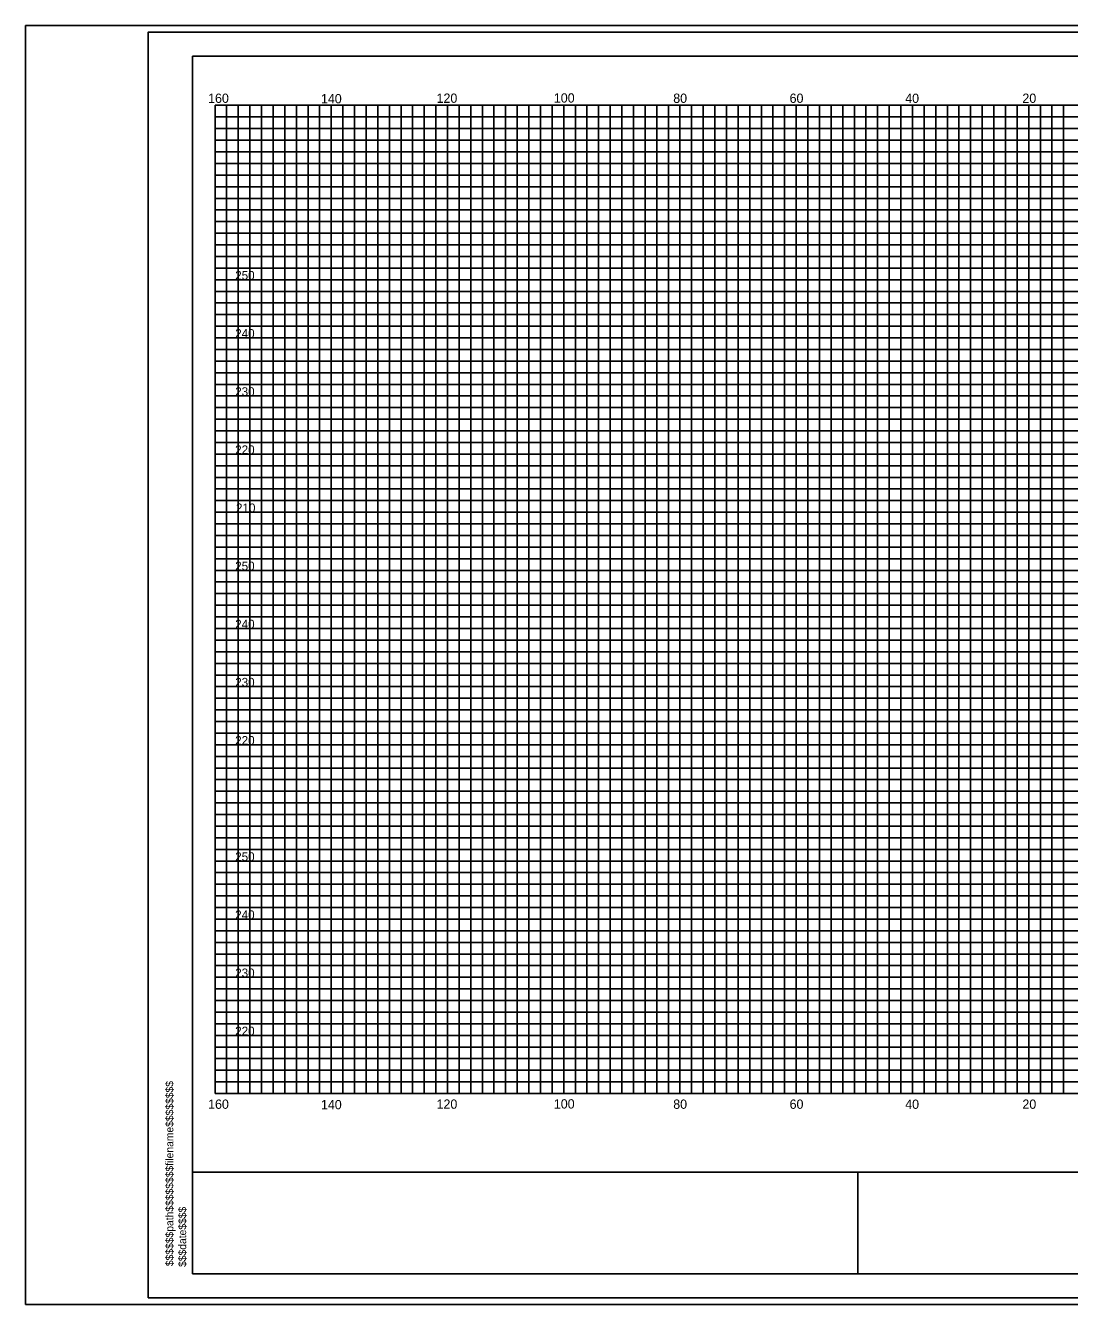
# Model space of a CAD drawing. Extents: x 967 to 1326, y 964 to 1744.
# Drawn here: x 967.4 to 1147, y 1243.7 to 1463.7 of the extents above; entities that cross this region are included whole.
import ezdxf

# ---------------------------------------------------------------- set-up
doc = ezdxf.new("R2010")
doc.units = 0
for name, color, linetype in [('Default', 7, 'Continuous'), ('RD_PD_PaveShd', 7, 'Continuous'), ('RD_XS_CurbBase', 7, 'Continuous'), ('RD_XS_TX_Elev_PR', 7, 'Continuous'), ('RD_XS_TX_MkPT', 7, 'Continuous'), ('RD_XS_TX_Slope', 7, 'Continuous'), ('RD_XS_TX_TOC', 7, 'Continuous')]:
    doc.layers.add(name, color=color, linetype=linetype)

msp = doc.modelspace()

# ---------------------------------------------------------------- linework, layer by layer
at = {"layer": 'RD_PD_PaveShd'}
for p, q in [((996.11, 1248.98), (996.11, 1458.46)), ((996.11, 1458.46), (1323.89, 1458.46)), ((996.11, 1266.49), (1323.89, 1266.49)), ((1110.59, 1248.98), (1110.59, 1266.56)), ((1323.89, 1248.98), (996.11, 1248.98))]:
    msp.add_line(p, q, dxfattribs=at)
at = {"layer": 'RD_XS_CurbBase'}
msp.add_lwpolyline([(967.41, 1243.72), (1326.28, 1243.72), (1326.28, 1463.72), (967.41, 1463.72)], close=True, dxfattribs=at)
at = {"layer": 'RD_XS_TX_Elev_PR'}
for p, q in [((1000, 1450), (1320, 1450)), ((1000, 1280), (1000, 1450)), ((1010, 1280), (1010, 1450)), ((1020, 1280), (1020, 1450)), ((1030, 1280), (1030, 1450)), ((1040, 1280), (1040, 1450)), ((1050, 1280), (1050, 1450)), ((1060, 1280), (1060, 1450)), ((1070, 1280), (1070, 1450)), ((1080, 1280), (1080, 1450)), ((1090, 1280), (1090, 1450)), ((1100, 1280), (1100, 1450)), ((1110, 1280), (1110, 1450)), ((1120, 1280), (1120, 1450)), ((1130, 1280), (1130, 1450)), ((1140, 1280), (1140, 1450)), ((1000, 1440), (1320, 1440)), ((1000, 1430), (1320, 1430)), ((1000, 1420), (1320, 1420)), ((1000, 1410), (1320, 1410)), ((1000, 1400), (1320, 1400)), ((1000, 1390), (1320, 1390)), ((1000, 1380), (1320, 1380)), ((1000, 1370), (1320, 1370)), ((1000, 1360), (1320, 1360)), ((1000, 1350), (1320, 1350)), ((1000, 1340), (1320, 1340)), ((1000, 1330), (1320, 1330)), ((1000, 1320), (1320, 1320)), ((1000, 1310), (1320, 1310)), ((1000, 1300), (1320, 1300)), ((1000, 1290), (1320, 1290)), ((1000, 1280), (1320, 1280))]:
    msp.add_line(p, q, dxfattribs=at)
at = {"layer": 'RD_XS_TX_Slope'}
for p, q in [((1002, 1280), (1002, 1450)), ((1004, 1280), (1004, 1450)), ((1006, 1280), (1006, 1450)), ((1008, 1280), (1008, 1450)), ((1012, 1280), (1012, 1450)), ((1014, 1280), (1014, 1450)), ((1016, 1280), (1016, 1450)), ((1018, 1280), (1018, 1450)), ((1022, 1280), (1022, 1450)), ((1024, 1280), (1024, 1450)), ((1026, 1280), (1026, 1450)), ((1028, 1280), (1028, 1450)), ((1032, 1280), (1032, 1450)), ((1034, 1280), (1034, 1450)), ((1036, 1280), (1036, 1450)), ((1038, 1280), (1038, 1450)), ((1042, 1280), (1042, 1450)), ((1044, 1280), (1044, 1450)), ((1046, 1280), (1046, 1450)), ((1048, 1280), (1048, 1450)), ((1052, 1280), (1052, 1450)), ((1054, 1280), (1054, 1450)), ((1056, 1280), (1056, 1450)), ((1058, 1280), (1058, 1450)), ((1062, 1280), (1062, 1450)), ((1064, 1280), (1064, 1450)), ((1066, 1280), (1066, 1450)), ((1068, 1280), (1068, 1450)), ((1072, 1280), (1072, 1450)), ((1074, 1280), (1074, 1450)), ((1076, 1280), (1076, 1450)), ((1078, 1280), (1078, 1450)), ((1082, 1280), (1082, 1450)), ((1084, 1280), (1084, 1450)), ((1086, 1280), (1086, 1450)), ((1088, 1280), (1088, 1450)), ((1092, 1280), (1092, 1450)), ((1094, 1280), (1094, 1450)), ((1096, 1280), (1096, 1450)), ((1098, 1280), (1098, 1450)), ((1102, 1280), (1102, 1450)), ((1104, 1280), (1104, 1450)), ((1106, 1280), (1106, 1450)), ((1108, 1280), (1108, 1450)), ((1112, 1280), (1112, 1450)), ((1114, 1280), (1114, 1450)), ((1116, 1280), (1116, 1450)), ((1118, 1280), (1118, 1450)), ((1122, 1280), (1122, 1450)), ((1124, 1280), (1124, 1450)), ((1126, 1280), (1126, 1450)), ((1128, 1280), (1128, 1450)), ((1132, 1280), (1132, 1450)), ((1134, 1280), (1134, 1450)), ((1136, 1280), (1136, 1450)), ((1138, 1280), (1138, 1450)), ((1142, 1280), (1142, 1450)), ((1144, 1280), (1144, 1450)), ((1146, 1280), (1146, 1450)), ((1000, 1448), (1320, 1448)), ((1000, 1446), (1320, 1446)), ((1000, 1444), (1320, 1444)), ((1000, 1442), (1320, 1442)), ((1000, 1438), (1320, 1438)), ((1000, 1436), (1320, 1436)), ((1000, 1434), (1320, 1434)), ((1000, 1432), (1320, 1432)), ((1000, 1428), (1320, 1428)), ((1000, 1426), (1320, 1426)), ((1000, 1424), (1320, 1424)), ((1000, 1422), (1320, 1422)), ((1000, 1418), (1320, 1418)), ((1000, 1416), (1320, 1416)), ((1000, 1414), (1320, 1414)), ((1000, 1412), (1320, 1412)), ((1000, 1408), (1320, 1408)), ((1000, 1406), (1320, 1406)), ((1000, 1404), (1320, 1404)), ((1000, 1402), (1320, 1402)), ((1000, 1398), (1320, 1398)), ((1000, 1396), (1320, 1396)), ((1000, 1394), (1320, 1394)), ((1000, 1392), (1320, 1392)), ((1000, 1388), (1320, 1388)), ((1000, 1386), (1320, 1386)), ((1000, 1384), (1320, 1384)), ((1000, 1382), (1320, 1382)), ((1000, 1378), (1320, 1378)), ((1000, 1376), (1320, 1376)), ((1000, 1374), (1320, 1374)), ((1000, 1372), (1320, 1372)), ((1000, 1368), (1320, 1368)), ((1000, 1366), (1320, 1366)), ((1000, 1364), (1320, 1364)), ((1000, 1362), (1320, 1362)), ((1000, 1358), (1320, 1358)), ((1000, 1356), (1320, 1356)), ((1000, 1354), (1320, 1354)), ((1000, 1352), (1320, 1352)), ((1000, 1348), (1320, 1348)), ((1000, 1346), (1320, 1346)), ((1000, 1344), (1320, 1344)), ((1000, 1342), (1320, 1342)), ((1000, 1338), (1320, 1338)), ((1000, 1336), (1320, 1336)), ((1000, 1334), (1320, 1334)), ((1000, 1332), (1320, 1332)), ((1000, 1328), (1320, 1328)), ((1000, 1326), (1320, 1326)), ((1000, 1324), (1320, 1324)), ((1000, 1322), (1320, 1322)), ((1000, 1318), (1320, 1318)), ((1000, 1316), (1320, 1316)), ((1000, 1314), (1320, 1314)), ((1000, 1312), (1320, 1312)), ((1000, 1308), (1320, 1308)), ((1000, 1306), (1320, 1306)), ((1000, 1304), (1320, 1304)), ((1000, 1302), (1320, 1302)), ((1000, 1298), (1320, 1298)), ((1000, 1296), (1320, 1296)), ((1000, 1294), (1320, 1294)), ((1000, 1292), (1320, 1292)), ((1000, 1288), (1320, 1288)), ((1000, 1286), (1320, 1286)), ((1000, 1284), (1320, 1284)), ((1000, 1282), (1320, 1282))]:
    msp.add_line(p, q, dxfattribs=at)
at = {"layer": 'RD_XS_TX_TOC'}
for points in [[(967.41, 1243.72), (1326.28, 1243.72), (1326.28, 1463.72), (967.41, 1463.72)], [(988.52, 1244.84), (1326.28, 1244.84), (1326.28, 1462.6), (988.52, 1462.6)]]:
    msp.add_lwpolyline(points, close=True, dxfattribs=at)

# ---------------------------------------------------------------- texts
at = {"layer": 'Default'}
for s, p in [('250', (1003.47, 1420)), ('240', (1003.47, 1410)), ('230', (1003.47, 1400)), ('220', (1003.47, 1390)), ('210', (1003.61, 1380)), ('250', (1003.47, 1370)), ('240', (1003.47, 1360)), ('230', (1003.47, 1350)), ('220', (1003.47, 1340)), ('250', (1003.47, 1320)), ('240', (1003.47, 1310)), ('230', (1003.47, 1300)), ('220', (1003.47, 1290))]:
    msp.add_text(s, height=1.5, dxfattribs=at).set_placement(p)
for s, p in [('$$$$$$path$$$$$$$$filename$$$$$$$$', (992.83, 1250.31)), ('$$$date$$$$', (995.04, 1250.17))]:
    msp.add_text(s, height=1.3258, rotation=90, dxfattribs=at).set_placement(p)
at = {"layer": 'RD_XS_TX_MkPT'}
for s, p in [('160', (998.81, 1450.42)), ('120', (1038.12, 1450.43)), ('100', (1058.3, 1450.47)), ('80', (1078.84, 1450.42)), ('60', (1098.86, 1450.42)), ('40', (1118.75, 1450.41)), ('20', (1138.91, 1450.42)), ('140', (1018.23, 1450.34)), ('160', (998.81, 1277.37)), ('140', (1018.23, 1277.29)), ('120', (1038.12, 1277.38)), ('100', (1058.3, 1277.42)), ('80', (1078.84, 1277.37)), ('60', (1098.86, 1277.37)), ('40', (1118.75, 1277.36)), ('20', (1138.91, 1277.37))]:
    msp.add_text(s, height=1.6, dxfattribs=at).set_placement(p)

doc.saveas('drawing.dxf')
